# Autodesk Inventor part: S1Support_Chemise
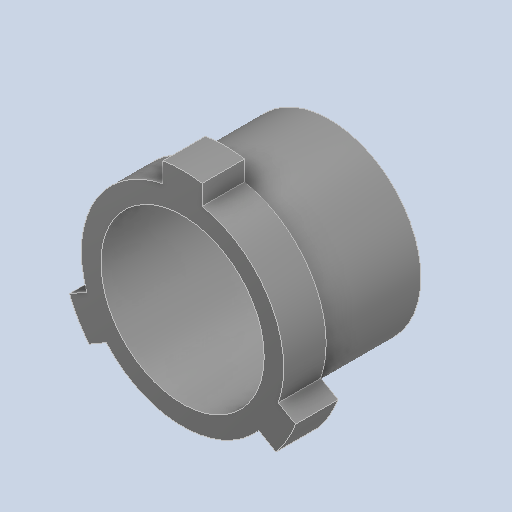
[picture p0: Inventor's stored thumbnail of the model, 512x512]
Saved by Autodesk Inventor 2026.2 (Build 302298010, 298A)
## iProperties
Created: 1601-01
Part Number: S1Support_Chemise
Material: Silicon Rubber
Document SubType Name: Modeling
Designer: mel
Density: 1.2465 g/cm^3
Appearance: glossy rubber
Author: mel
Sending System: SOLIDWORKS 2023
Part Number: Support_Chemise
Last Saved Date: 2025-04-02
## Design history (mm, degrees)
feature "Boss.-Extru.3"
node "Solide1"
